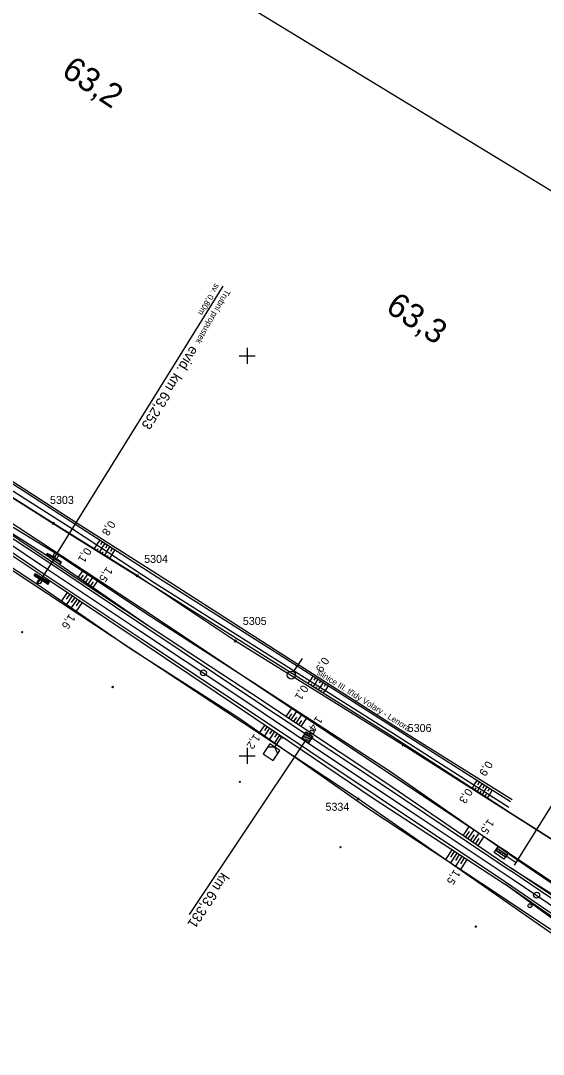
# Model space of a CAD drawing. Extents: x -804899 to -803847, y -1165742 to -1164942.
# Drawn here: x -804356.6 to -804226, y -1165474.6 to -1165216.2 of the extents above; entities that cross this region are included whole.
import ezdxf

# ---------------------------------------------------------------- set-up
doc = ezdxf.new("R2010")
doc.units = 0
for name, color, linetype in [('0381KM061-064P - Vrstva 1', 7, 'Continuous'), ('0381KM061-064P - Vrstva 13', 7, 'Continuous'), ('0381KM061-064P - Vrstva 17', 7, 'Continuous'), ('0381KM061-064P - Vrstva 19', 7, 'Continuous'), ('0381KM061-064P - Vrstva 27', 7, 'Continuous'), ('0381KM061-064P - Vrstva 3', 7, 'Continuous'), ('0381KM061-064P - Vrstva 36', 7, 'Continuous'), ('0381KM061-064P - Vrstva 4', 7, 'Continuous'), ('0381KM061-064P - Vrstva 48', 7, 'Continuous'), ('0381KM061-064P - Vrstva 49', 7, 'Continuous'), ('0381KM061-064P - Vrstva 51', 7, 'Continuous'), ('0381KM061-064P - Vrstva 55', 7, 'Continuous'), ('0381KM061-064P - Vrstva 7', 7, 'Continuous'), ('0381KM061-064P - Vrstva 8', 7, 'Continuous'), ('formát', 7, 'Continuous'), ('krizky_1000 - Vrstva 1', 7, 'Continuous'), ('szdc - hran DP', 7, 'Continuous'), ('szdc - szdc_cislo', 7, 'Continuous'), ('szdc - szdc_krizek', 7, 'Continuous')]:
    doc.layers.add(name, color=color, linetype=linetype)

msp = doc.modelspace()

# ---------------------------------------------------------------- linework, layer by layer
at = {"layer": '0381KM061-064P - Vrstva 1'}
for points in [[(-804619.36, -1165173.74), (-804594.78, -1165190.05), (-804577, -1165201.91), (-804561.16, -1165212.47), (-804538.32, -1165227.67), (-804515.3, -1165243.02), (-804489.41, -1165260.27), (-804477.81, -1165268), (-804447.6, -1165288.14), (-804422.03, -1165305.2), (-804398.19, -1165321.09), (-804394.23, -1165323.73), (-804371.85, -1165338.65), (-804349.9, -1165353.29), (-804326.64, -1165368.8), (-804303.84, -1165384.01), (-804280.33, -1165399.7), (-804257.04, -1165415.23), (-804233.85, -1165430.69)], [(-804233.85, -1165430.69), (-804221.71, -1165438.86), (-804209.06, -1165447.77)]]:
    msp.add_lwpolyline(points, dxfattribs=at)
at = {"layer": '0381KM061-064P - Vrstva 13'}
for points in [[(-804348.53, -1165350.16), (-804348.11, -1165349.19), (-804347.55, -1165349.48)], [(-804347.71, -1165350.75), (-804347.06, -1165350.02), (-804347.55, -1165349.48)], [(-804351.94, -1165355.72), (-804352.52, -1165356.42), (-804352.55, -1165356.96)], [(-804351.23, -1165356.15), (-804351.73, -1165356.92), (-804352.55, -1165356.96)]]:
    msp.add_lwpolyline(points, dxfattribs=at)
for centre, major_axis, ratio, start_param, end_param in [((-804348.06, -1165350.36), (0.502, -0.373), 0.294364, 3.805363, 5.70381), ((-804351.59, -1165355.94), (-0.372, 0.23), 0.069899, 3.50752, 6.025727)]:
    msp.add_ellipse(centre, major_axis=major_axis, ratio=ratio, start_param=start_param, end_param=end_param, dxfattribs=at)
at = {"layer": '0381KM061-064P - Vrstva 17'}
for points in [[(-804349.85, -1165349.62), (-804346.55, -1165351.67)], [(-804349.69, -1165356.94), (-804352.99, -1165354.74)]]:
    msp.add_lwpolyline(points, dxfattribs=at)
at = {"layer": '0381KM061-064P - Vrstva 19'}
for p, q in [((-804348.23, -1165350.54), (-804306.04, -1165282.63)), ((-804348.12, -1165350.55), (-804351.58, -1165355.92))]:
    msp.add_line(p, q, dxfattribs=at)
for points in [[(-804350.13, -1165349.85), (-804349.96, -1165349.4), (-804349.94, -1165349.53)], [(-804346.52, -1165351.56), (-804349.94, -1165349.53), (-804350.13, -1165349.85), (-804346.84, -1165352.14), (-804346.52, -1165351.56)], [(-804349.96, -1165349.4), (-804348.53, -1165350.16)], [(-804346.41, -1165351.59), (-804347.71, -1165350.75)], [(-804346.84, -1165352.14), (-804346.41, -1165351.59), (-804346.52, -1165351.56)], [(-804353.14, -1165354.84), (-804353.21, -1165354.88), (-804352.95, -1165354.5)], [(-804353.14, -1165354.84), (-804349.82, -1165357.01), (-804349.52, -1165356.59), (-804352.95, -1165354.5), (-804353.14, -1165354.84)], [(-804353.21, -1165354.88), (-804351.94, -1165355.72)], [(-804349.84, -1165357.12), (-804351.23, -1165356.15)], [(-804349.52, -1165356.59), (-804349.84, -1165357.12), (-804349.82, -1165357.01)]]:
    msp.add_lwpolyline(points, dxfattribs=at)
for centre, major_axis, ratio, start_param, end_param in [((-804348.14, -1165350.46), (-0.469, 0.338), 0.066779, 5.748415, 9.878714), ((-804348.06, -1165350.36), (0.502, -0.373), 0.294364, 3.805363, 5.70381), ((-804351.59, -1165355.96), (-0.405, 0.253), 0.126448, 5.826099, 9.990944), ((-804351.59, -1165355.94), (-0.372, 0.23), 0.069899, 3.50752, 6.025727)]:
    msp.add_ellipse(centre, major_axis=major_axis, ratio=ratio, start_param=start_param, end_param=end_param, dxfattribs=at)
at = {"layer": '0381KM061-064P - Vrstva 27'}
msp.add_line((-804283.87, -1165394.04), (-804283.77, -1165394.04), dxfattribs=at)
msp.add_circle((-804283.82, -1165394.04), 0.5, dxfattribs=at)
at = {"layer": '0381KM061-064P - Vrstva 3'}
for p, q in [((-804283.6, -1165395.11), (-804286.38, -1165395.66)), ((-804284.05, -1165394.82), (-804286.08, -1165395.22)), ((-804283.9, -1165395.55), (-804285.94, -1165395.96)), ((-804284.49, -1165394.52), (-804285.79, -1165394.78)), ((-804284.93, -1165394.23), (-804285.5, -1165394.34)), ((-804284.19, -1165395.99), (-804285.5, -1165396.25)), ((-804285.55, -1165396.22), (-804314.54, -1165439.64)), ((-804284.49, -1165396.43), (-804285.06, -1165396.55))]:
    msp.add_line(p, q, dxfattribs=at)
msp.add_lwpolyline([(-804284.72, -1165396.77), (-804286.38, -1165395.66), (-804285.27, -1165394), (-804283.6, -1165395.11)], close=True, dxfattribs=at)
at = {"layer": '0381KM061-064P - Vrstva 36'}
for p, q in [((-804288.43, -1165378.96), (-804286.21, -1165375.63)), ((-804288.99, -1165379.79), (-804288.99, -1165379.79))]:
    msp.add_line(p, q, dxfattribs=at)
msp.add_circle((-804288.99, -1165379.79), 1, dxfattribs=at)
at = {"layer": '0381KM061-064P - Vrstva 4'}
for points in [[(-804755.73, -1165115.93), (-804748.17, -1165116.91), (-804721.25, -1165123.25), (-804698.66, -1165130.22), (-804681.33, -1165136.99), (-804671.47, -1165141.65), (-804648.84, -1165153.36), (-804638.11, -1165160.03), (-804624.48, -1165168.7), (-804602.56, -1165183.07), (-804574.47, -1165201.72), (-804542.72, -1165222.84), (-804507.36, -1165246.55), (-804477.08, -1165266.82), (-804448.75, -1165285.88), (-804421.18, -1165304.15), (-804392.89, -1165323.09), (-804369.85, -1165338.37), (-804348.86, -1165352.04), (-804325.13, -1165367.98), (-804299.32, -1165385.27), (-804266.05, -1165407.31), (-804234.28, -1165428.6)], [(-804755.73, -1165115.93), (-804748.03, -1165116.49), (-804721.05, -1165122.36), (-804698.44, -1165129.77), (-804680.98, -1165136.5), (-804671.21, -1165140.89), (-804648.42, -1165152.46), (-804637.55, -1165159.43), (-804624.04, -1165168.29), (-804602.25, -1165182.38), (-804573.74, -1165201.2), (-804542.46, -1165222.56), (-804507.06, -1165246.03), (-804476.47, -1165266.24), (-804448.31, -1165285.08), (-804421.02, -1165303.1), (-804392.59, -1165322.59), (-804369.41, -1165337.65), (-804348.68, -1165351.59), (-804324.76, -1165367.42), (-804298.9, -1165384.42), (-804265.65, -1165406.5), (-804234.05, -1165428.04)], [(-804626.64, -1165171.43), (-804605.18, -1165186.34), (-804576.91, -1165204.69), (-804544.69, -1165226.09), (-804509.35, -1165249.3), (-804478.87, -1165269.77), (-804450.06, -1165288.98), (-804422.82, -1165307.11), (-804394.42, -1165325.66), (-804371.77, -1165341.24), (-804350.46, -1165355.38), (-804326.73, -1165371.34), (-804301.47, -1165388.34), (-804268.3, -1165410.72), (-804235.74, -1165432.01)], [(-804576.36, -1165204.15), (-804544.19, -1165225.52), (-804508.95, -1165249), (-804478.52, -1165269.18), (-804449.67, -1165288.56), (-804422.62, -1165306.58), (-804394.22, -1165325.33), (-804371.37, -1165340.61), (-804350.54, -1165354.66), (-804326.31, -1165370.81), (-804300.9, -1165387.72), (-804267.8, -1165409.92), (-804235.52, -1165431.44)], [(-804208.29, -1165446.31), (-804234.28, -1165428.6)], [(-804207.68, -1165445.74), (-804234.05, -1165428.04)], [(-804210.55, -1165449.47), (-804235.74, -1165432.01)], [(-804235.52, -1165431.44), (-804210.13, -1165448.78)]]:
    msp.add_lwpolyline(points, dxfattribs=at)
at = {"layer": '0381KM061-064P - Vrstva 48'}
for p, q in [((-804337.56, -1165347.25), (-804336.79, -1165346.06)), ((-804336.62, -1165347.19), (-804336.16, -1165346.47)), ((-804336.3, -1165348.08), (-804335.53, -1165346.88)), ((-804338.21, -1165348.31), (-804337.55, -1165347.26)), ((-804337.57, -1165348.71), (-804337.25, -1165348.19)), ((-804336.93, -1165349.11), (-804336.29, -1165348.08)), ((-804336.3, -1165349.51), (-804335.98, -1165349)), ((-804335.66, -1165349.9), (-804335.04, -1165348.91)), ((-804335.36, -1165348.01), (-804334.9, -1165347.28)), ((-804335.05, -1165348.91), (-804334.27, -1165347.69)), ((-804334.11, -1165348.83), (-804333.64, -1165348.1)), ((-804333.8, -1165349.73), (-804333.01, -1165348.51)), ((-804335.03, -1165350.3), (-804334.72, -1165349.81)), ((-804334.39, -1165350.7), (-804333.79, -1165349.74)), ((-804341.15, -1165353.74), (-804342.25, -1165355.32)), ((-804340.97, -1165354.79), (-804341.63, -1165355.74)), ((-804339.9, -1165354.57), (-804341.01, -1165356.17)), ((-804339.73, -1165355.63), (-804340.4, -1165356.6)), ((-804338.66, -1165355.4), (-804339.78, -1165357.02)), ((-804338.48, -1165356.47), (-804339.16, -1165357.45)), ((-804337.41, -1165356.23), (-804338.55, -1165357.88)), ((-804346.34, -1165361.27), (-804344.9, -1165359.12)), ((-804345.15, -1165360.83), (-804344.27, -1165359.54)), ((-804345.11, -1165362.12), (-804343.65, -1165359.96)), ((-804343.91, -1165361.68), (-804343.03, -1165360.37)), ((-804343.88, -1165362.98), (-804342.41, -1165360.79)), ((-804342.67, -1165362.53), (-804341.79, -1165361.21)), ((-804342.64, -1165363.83), (-804341.16, -1165361.63)), ((-804283.59, -1165380.05), (-804284.34, -1165381.22)), ((-804282.96, -1165380.46), (-804283.33, -1165381.04)), ((-804284.75, -1165381.87), (-804284.34, -1165381.22)), ((-804284.11, -1165382.27), (-804283.91, -1165381.95)), ((-804283.48, -1165382.67), (-804283.07, -1165382.02)), ((-804282.33, -1165380.86), (-804283.07, -1165382.02)), ((-804282.85, -1165383.07), (-804282.64, -1165382.75)), ((-804282.21, -1165383.47), (-804281.81, -1165382.82)), ((-804281.7, -1165381.26), (-804282.07, -1165381.84)), ((-804281.06, -1165381.67), (-804281.8, -1165382.82)), ((-804280.43, -1165382.07), (-804280.8, -1165382.65)), ((-804279.8, -1165382.47), (-804280.54, -1165383.63)), ((-804281.58, -1165383.87), (-804281.37, -1165383.55)), ((-804280.94, -1165384.27), (-804280.54, -1165383.62)), ((-804290.26, -1165390.16), (-804288.8, -1165387.95)), ((-804289.64, -1165390.57), (-804288.9, -1165389.46)), ((-804289.01, -1165390.98), (-804287.54, -1165388.76)), ((-804288.39, -1165391.4), (-804287.65, -1165390.29)), ((-804287.76, -1165391.81), (-804286.28, -1165389.58)), ((-804286.51, -1165392.64), (-804285.02, -1165390.4)), ((-804295.65, -1165392.27), (-804296.91, -1165394.13)), ((-804294.41, -1165393.1), (-804295.68, -1165394.99)), ((-804295.03, -1165392.69), (-804295.66, -1165393.62)), ((-804293.79, -1165393.53), (-804294.43, -1165394.47)), ((-804287.14, -1165392.23), (-804286.4, -1165391.11)), ((-804293.17, -1165393.94), (-804294.45, -1165395.85)), ((-804291.92, -1165394.78), (-804293.22, -1165396.71)), ((-804292.54, -1165394.36), (-804293.19, -1165395.32)), ((-804243.31, -1165407.27), (-804242.59, -1165406.14)), ((-804243.31, -1165407.27), (-804243.8, -1165408.03)), ((-804242.88, -1165407.98), (-804243.17, -1165408.43)), ((-804242.05, -1165408.07), (-804242.54, -1165408.84)), ((-804242.39, -1165407.22), (-804241.96, -1165406.54)), ((-804242.05, -1165408.07), (-804241.33, -1165406.94)), ((-804241.61, -1165408.79), (-804241.91, -1165409.25)), ((-804240.78, -1165408.88), (-804241.29, -1165409.66)), ((-804241.13, -1165408.02), (-804240.69, -1165407.34)), ((-804240.78, -1165408.88), (-804240.06, -1165407.74)), ((-804239.86, -1165408.83), (-804239.43, -1165408.15)), ((-804239.52, -1165409.69), (-804238.8, -1165408.55)), ((-804240.35, -1165409.6), (-804240.66, -1165410.06)), ((-804239.52, -1165409.69), (-804240.03, -1165410.47)), ((-804244.59, -1165417.6), (-804246.1, -1165419.82)), ((-804244.58, -1165418.91), (-804245.48, -1165420.24)), ((-804243.36, -1165418.45), (-804244.86, -1165420.66)), ((-804242.13, -1165419.31), (-804243.62, -1165421.51)), ((-804243.34, -1165419.76), (-804244.24, -1165421.09)), ((-804242.11, -1165420.61), (-804243.01, -1165421.93)), ((-804240.9, -1165420.17), (-804242.39, -1165422.35)), ((-804250.43, -1165425.88), (-804248.84, -1165423.45)), ((-804249.18, -1165426.71), (-804247.58, -1165424.27)), ((-804249.17, -1165425.32), (-804248.21, -1165423.85)), ((-804247.93, -1165427.54), (-804246.33, -1165425.09)), ((-804247.91, -1165426.15), (-804246.95, -1165424.68)), ((-804246.68, -1165428.37), (-804245.07, -1165425.91)), ((-804246.66, -1165426.97), (-804245.7, -1165425.5))]:
    msp.add_line(p, q, dxfattribs=at)
at = {"layer": '0381KM061-064P - Vrstva 49'}
for p, q in [((-804356.09, -1165369.23), (-804356.44, -1165368.87)), ((-804356.09, -1165368.87), (-804356.44, -1165369.23)), ((-804333.45, -1165382.97), (-804333.81, -1165382.62)), ((-804333.45, -1165382.62), (-804333.81, -1165382.97)), ((-804301.7, -1165406.66), (-804302.06, -1165406.31)), ((-804301.7, -1165406.31), (-804302.06, -1165406.66)), ((-804276.5, -1165422.97), (-804276.85, -1165422.62)), ((-804276.5, -1165422.62), (-804276.85, -1165422.97)), ((-804242.71, -1165442.85), (-804243.07, -1165442.5)), ((-804242.71, -1165442.5), (-804243.07, -1165442.85))]:
    msp.add_line(p, q, dxfattribs=at)
for points in [[(-804668.09, -1165135.13), (-804646.08, -1165148.91), (-804635.34, -1165155.79), (-804621.98, -1165164.4), (-804599.68, -1165178.86), (-804570.23, -1165197.63), (-804539.04, -1165217.4), (-804503.79, -1165239.32), (-804473.21, -1165259.25), (-804445.02, -1165277.37), (-804416.3, -1165295.6), (-804385.23, -1165314.87), (-804342.84, -1165342.16), (-804322.16, -1165355.5), (-804292.15, -1165374.6), (-804262.58, -1165393.44), (-804234.25, -1165411.43)], [(-804668.53, -1165136.56), (-804646.51, -1165150.38), (-804635.75, -1165157.19), (-804622.88, -1165165.28), (-804600.74, -1165180), (-804571.06, -1165199.05), (-804539.91, -1165219.23), (-804504.85, -1165241.38), (-804474.07, -1165260.59), (-804445.75, -1165278.86), (-804417.38, -1165297.08), (-804386.13, -1165316.29), (-804343.68, -1165343.22), (-804323.05, -1165356.81), (-804293.41, -1165375.48), (-804263.45, -1165394.43), (-804234.68, -1165412.78)], [(-804576.91, -1165204.69), (-804544.69, -1165226.09), (-804509.35, -1165249.3), (-804478.87, -1165269.77), (-804450.06, -1165288.98), (-804422.82, -1165307.11), (-804394.42, -1165325.66), (-804371.77, -1165341.24), (-804350.46, -1165355.38), (-804326.73, -1165371.34), (-804301.47, -1165388.34), (-804268.3, -1165410.72), (-804235.74, -1165432.01)], [(-804474.97, -1165261.14), (-804446.16, -1165279.93), (-804417.55, -1165297.62), (-804371.56, -1165327.37), (-804344.89, -1165344.14), (-804323.3, -1165357.63), (-804293.83, -1165376.15), (-804263.84, -1165395.04), (-804235.23, -1165413.58)], [(-804475.98, -1165263.3), (-804448.01, -1165281.64), (-804419.88, -1165300.43), (-804390.2, -1165320.54), (-804368.79, -1165336.61), (-804347.55, -1165349.48), (-804323.92, -1165365.2), (-804298.45, -1165381.67), (-804264.49, -1165403.75), (-804232.5, -1165426.01)], [(-804424.02, -1165310.32), (-804397.08, -1165327.6), (-804372.3, -1165344.03), (-804352.55, -1165356.96), (-804329.59, -1165372.88)], [(-804369.41, -1165337.65), (-804350.13, -1165349.85)], [(-804348.53, -1165350.16), (-804349.96, -1165349.4), (-804350.13, -1165349.85)], [(-804348.12, -1165350.55), (-804347.55, -1165349.48)], [(-804346.84, -1165352.14), (-804346.41, -1165351.59), (-804347.71, -1165350.75)], [(-804346.84, -1165352.14), (-804324.76, -1165367.42)], [(-804351.94, -1165355.72), (-804353.21, -1165354.88), (-804352.95, -1165354.5), (-804349.52, -1165356.59), (-804349.84, -1165357.12), (-804351.23, -1165356.15)], [(-804351.58, -1165355.92), (-804352.55, -1165356.96)], [(-804324.76, -1165367.42), (-804298.9, -1165384.42), (-804265.65, -1165406.5), (-804234.05, -1165428.04)], [(-804329.59, -1165372.88), (-804302.32, -1165390.35), (-804269.85, -1165413.05), (-804237.3, -1165434.57)], [(-804232.5, -1165426.01), (-804205.4, -1165444.42), (-804185.08, -1165460.87), (-804164.82, -1165478.77), (-804146.89, -1165498.25)], [(-804234.05, -1165428.04), (-804207.28, -1165445), (-804187.24, -1165461.29), (-804165.68, -1165480.42), (-804149.47, -1165498.06), (-804149.78, -1165499.19)], [(-804211.12, -1165449.96), (-804235.74, -1165432.01)], [(-804237.3, -1165434.57), (-804211.51, -1165451.84), (-804192.43, -1165466.88), (-804171.52, -1165486.4), (-804154.9, -1165505.76)]]:
    msp.add_lwpolyline(points, dxfattribs=at)
for centre, major_axis, ratio, start_param, end_param in [((-804348.06, -1165350.36), (0.502, -0.373), 0.294364, 3.805363, 5.70381), ((-804351.59, -1165355.94), (-0.372, 0.23), 0.069899, 3.50752, 6.025727)]:
    msp.add_ellipse(centre, major_axis=major_axis, ratio=ratio, start_param=start_param, end_param=end_param, dxfattribs=at)
at = {"layer": '0381KM061-064P - Vrstva 51'}
msp.add_line((-804262.45, -1165392.96), (-804233.82, -1165410.93), dxfattribs=at)
msp.add_lwpolyline([(-804728.9, -1165105.9), (-804711.54, -1165108.67), (-804704.35, -1165111.8), (-804683.69, -1165124.09), (-804676.95, -1165128.43), (-804667.36, -1165134.41), (-804645.71, -1165148.3), (-804634.7, -1165155.23), (-804621.63, -1165163.62), (-804599.19, -1165178.23), (-804569.67, -1165197.16), (-804538.42, -1165216.77), (-804503.41, -1165238.94), (-804472.82, -1165258.55), (-804444.57, -1165276.4), (-804415.82, -1165294.73), (-804384.7, -1165314.57), (-804342.59, -1165341.72), (-804321.8, -1165355.02), (-804291.77, -1165374.22), (-804262.45, -1165392.96)], dxfattribs=at)
at = {"layer": '0381KM061-064P - Vrstva 55'}
msp.add_lwpolyline([(-804468.27, -1165264.32), (-804426.86, -1165291.43), (-804390.35, -1165315.35), (-804348.41, -1165341.86), (-804327.45, -1165354.94), (-804302.94, -1165371.26), (-804261.01, -1165397.26), (-804213.5, -1165427.44), (-804191.69, -1165441.88), (-804177.28, -1165451.4), (-804169.73, -1165458.18), (-804172.29, -1165470.42), (-804193.11, -1165453.43), (-804217.51, -1165435.77), (-804323.51, -1165365.07), (-804402.46, -1165313.29)], close=True, dxfattribs=at)
at = {"layer": '0381KM061-064P - Vrstva 7'}
for p, q in [((-804293.09, -1165397.82), (-804291.43, -1165395.33)), ((-804291.01, -1165395.61), (-804291.84, -1165395.05)), ((-804229.44, -1165437.43), (-804229.36, -1165437.49))]:
    msp.add_line(p, q, dxfattribs=at)
for points in [[(-804293.09, -1165397.82), (-804294.34, -1165396.99), (-804296, -1165399.49), (-804293.51, -1165401.15), (-804291.84, -1165398.66), (-804293.09, -1165397.82)], [(-804292.4, -1165399.49), (-804293.09, -1165397.82), (-804294.9, -1165397.82)]]:
    msp.add_lwpolyline(points, dxfattribs=at)
for centre, radius in [((-804310.94, -1165379.23), 0.75), ((-804227.7, -1165434.8), 0.75), ((-804229.4, -1165437.46), 0.5)]:
    msp.add_circle(centre, radius, dxfattribs=at)
at = {"layer": '0381KM061-064P - Vrstva 8'}
for p, q in [((-804232.81, -1165426.68), (-804194.18, -1165364.63)), ((-804236.98, -1165423.48), (-804237.94, -1165423.67)), ((-804237.42, -1165423.18), (-804237.73, -1165423.24)), ((-804236.54, -1165423.77), (-804237.5, -1165423.96)), ((-804236.09, -1165424.06), (-804237.06, -1165424.26)), ((-804235.65, -1165424.36), (-804236.62, -1165424.55)), ((-804235.21, -1165424.65), (-804236.18, -1165424.85)), ((-804235.33, -1165425.06), (-804235.74, -1165425.14)), ((-804233.22, -1165427.3), (-804232.39, -1165426.05))]:
    msp.add_line(p, q, dxfattribs=at)
for points in [[(-804235.86, -1165425.84), (-804238.35, -1165424.18), (-804237.24, -1165422.52), (-804234.75, -1165424.18), (-804235.86, -1165425.84)], [(-804235.3, -1165425.01), (-804232.81, -1165426.68)]]:
    msp.add_lwpolyline(points, dxfattribs=at)
msp.add_lwpolyline([(-804235.5, -1165425.3), (-804237.99, -1165423.64), (-804237.61, -1165423.06), (-804235.11, -1165424.72)], close=True, dxfattribs=at)
at = {"layer": 'formát'}
msp.add_line((-804206.05, -1165269.84), (-804743.98, -1164941.92), dxfattribs=at)
at = {"layer": 'krizky_1000 - Vrstva 1'}
for points in [[(-804302, -1165300), (-804298, -1165300)], [(-804300, -1165298), (-804300, -1165302)], [(-804300, -1165398), (-804300, -1165402)], [(-804302, -1165400), (-804298, -1165400)]]:
    msp.add_lwpolyline(points, dxfattribs=at)
at = {"layer": 'szdc - hran DP'}
for p, q in [((-804390.35, -1165315.35), (-804348.41, -1165341.86)), ((-804272.3, -1165410.7), (-804413.53, -1165317.49)), ((-804348.41, -1165341.86), (-804327.45, -1165354.94)), ((-804327.45, -1165354.94), (-804302.94, -1165371.26)), ((-804302.94, -1165371.26), (-804261.01, -1165397.26)), ((-804261.01, -1165397.26), (-804213.5, -1165427.44)), ((-804199.72, -1165461.33), (-804272.3, -1165410.7))]:
    msp.add_line(p, q, dxfattribs=at)
at = {"layer": 'szdc - szdc_krizek'}
for p, q in [((-804348.15, -1165342.12), (-804348.68, -1165341.59)), ((-804348.68, -1165342.12), (-804348.15, -1165341.59)), ((-804327.19, -1165355.21), (-804327.72, -1165354.68)), ((-804327.72, -1165355.21), (-804327.19, -1165354.68)), ((-804302.68, -1165371.53), (-804303.21, -1165371)), ((-804303.21, -1165371.53), (-804302.68, -1165371)), ((-804260.74, -1165397.53), (-804261.28, -1165397)), ((-804261.28, -1165397.53), (-804260.74, -1165397)), ((-804272.04, -1165410.97), (-804272.57, -1165410.44)), ((-804272.57, -1165410.97), (-804272.04, -1165410.44))]:
    msp.add_line(p, q, dxfattribs=at)

# ---------------------------------------------------------------- texts
at = {"layer": '0381KM061-064P - Vrstva 19'}
for s, height, rotation, p in [('sv. 0,80m', 1.5, 240.1321, (-804308.03, -1165281.79)), ('Trubní propustek', 1.5, 240.1321, (-804305.42, -1165283.29)), ('evid. km 63,253', 2.5, 238.1402, (-804314.07, -1165297.33))]:
    msp.add_text(s, height=height, rotation=rotation, dxfattribs=at).set_placement(p)
at = {"layer": '0381KM061-064P - Vrstva 3'}
msp.add_text('km 63,331', height=2.5, rotation=236.2785, dxfattribs=at).set_placement((-804306.42, -1165428.98))
at = {"layer": '0381KM061-064P - Vrstva 48'}
for s, rotation, p in [('0,8', 237.1733, (-804334.42, -1165341.01)), ('0,1', 238.0111, (-804340.44, -1165347.75)), ('1,5', 235.3116, (-804335.06, -1165352.61)), ('1,6', 236.0582, (-804344.4, -1165364.35)), ('0,9', 237.503, (-804281.05, -1165375.12)), ('0,1', 237.7998, (-804286.25, -1165382.09)), ('1,4', 236.4166, (-804282.66, -1165389.9)), ('1,2', 236.0013, (-804298.21, -1165394.34)), ('0,9', 237.5753, (-804240.19, -1165401.08)), ('0,3', 237.0482, (-804245.18, -1165407.93)), ('1,5', 235.7229, (-804239.75, -1165415.6)), ('1,5', 236.8157, (-804248.25, -1165428.23))]:
    msp.add_text(s, height=2, rotation=rotation, dxfattribs=at).set_placement(p)
at = {"layer": '0381KM061-064P - Vrstva 51'}
msp.add_text('silnice III. třídy Volary - Lenora', height=1.5, rotation=327.9008, dxfattribs=at).set_placement((-804282.76, -1165379.52))
at = {"layer": '0381KM061-064P - Vrstva 7'}
for s, rotation, p in [('63,2', 326.3093, (-804346.68, -1165229.73)), ('63,3', 326.3024, (-804265.71, -1165288.72))]:
    msp.add_text(s, height=6, rotation=rotation, dxfattribs=at).set_placement(p)
at = {"layer": 'szdc - szdc_cislo'}
for s, p in [('5303', (-804349.28, -1165337.02)), ('5304', (-804325.76, -1165351.76)), ('5305', (-804301.11, -1165367.27)), ('5306', (-804259.92, -1165394.02)), ('5334', (-804280.46, -1165413.71))]:
    msp.add_text(s, height=2, dxfattribs=at).set_placement(p)

doc.saveas('drawing.dxf')
